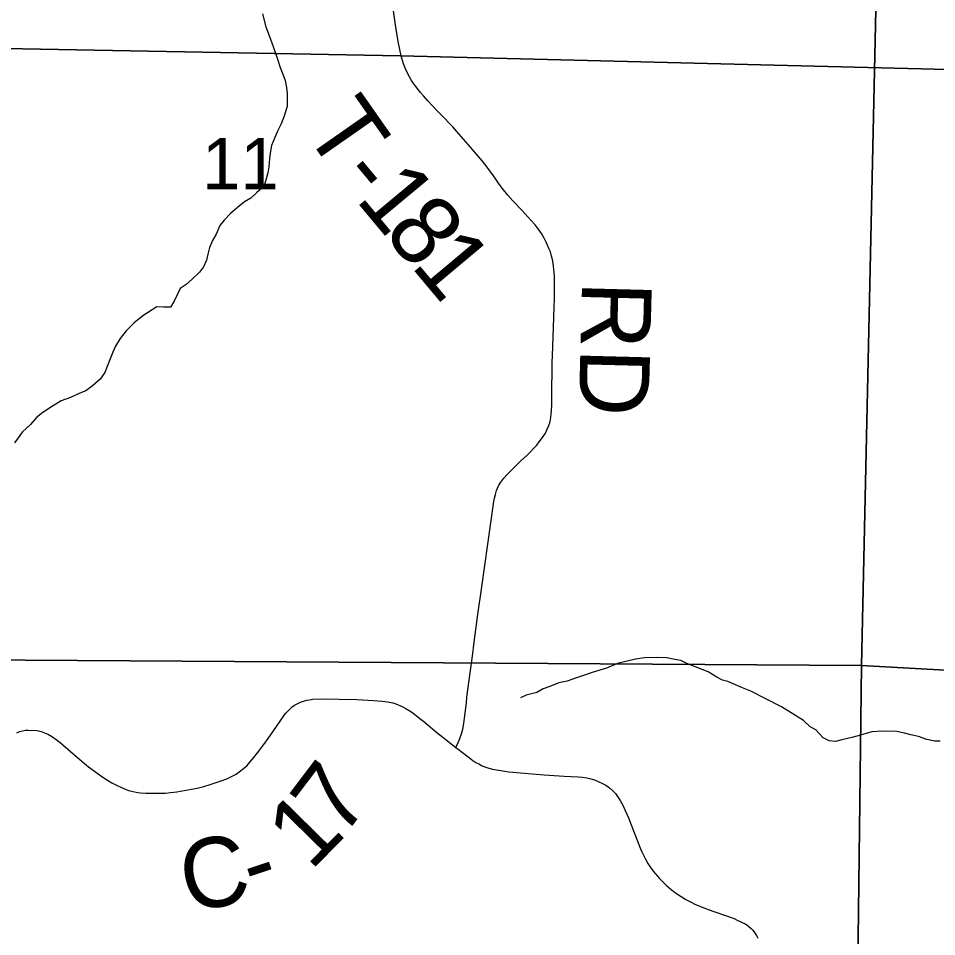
# Model space of a CAD drawing. Extents: x 0 to 34, y 0 to 22.
# Drawn here: x 13.784 to 14.532, y 16.764 to 17.512 of the extents above; entities that cross this region are included whole.
import ezdxf

# ---------------------------------------------------------------- set-up
doc = ezdxf.new("R2010")
doc.units = 0
for name, color, linetype in [('GM_X_Corporation', 7, 'Continuous'), ('GM_X_County_Road', 7, 'Continuous'), ('GM_X_County_Road_Text', 7, 'Continuous'), ('GM_X_Minor_River', 7, 'Continuous'), ('GM_X_Section_Text', 7, 'Continuous'), ('GM_X_Township_Road', 7, 'Continuous'), ('GM_X_Township_Road_Text', 7, 'Continuous')]:
    doc.layers.add(name, color=color, linetype=linetype)

msp = doc.modelspace()

# ---------------------------------------------------------------- linework, layer by layer
at = {"layer": 'GM_X_Corporation'}
for points in [[(13.27416, 17.49656), (14.09544, 17.48114), (14.72599, 17.4654), (14.75606, 17.4645), (15.84263, 17.42782), (15.88436, 17.42688), (16.48069, 17.41608), (16.48857, 17.73917), (16.51683, 18.87067), (16.5174, 18.89349), (16.54748, 18.89293), (16.75204, 18.88908), (16.75322, 19.06144), (16.75475, 19.28374), (16.76523, 20.32799), (16.7661, 20.4), (11.50006, 20.4)], [(16.44192, 14.8642), (16.44975, 15.46263), (16.45161, 15.59641), (16.46108, 16.1288), (16.46029, 16.26174), (16.46891, 16.92454), (16.47027, 17.00356), (16.4704, 17.01044), (16.48069, 17.41608), (15.88436, 17.42688), (15.84263, 17.42782), (14.75606, 17.4645), (14.72599, 17.4654), (14.09544, 17.48114), (13.27416, 17.49656)]]:
    msp.add_lwpolyline(points, dxfattribs=at)
for points in [[(13.4723, 18.00009), (14.4926, 17.9788), (14.47088, 16.98467), (13.4493, 16.99116)], [(14.4926, 17.9788), (15.50037, 17.94467), (15.48158, 16.92817), (14.47088, 16.98467)], [(13.4493, 16.99116), (14.47088, 16.98467), (14.45833, 15.96227), (13.43365, 15.97401)], [(14.47088, 16.98467), (15.48158, 16.92817), (15.46915, 15.91633), (14.45833, 15.96227)]]:
    msp.add_lwpolyline(points, close=True, dxfattribs=at)
at = {"layer": 'GM_X_County_Road'}
msp.add_lwpolyline([(13.78303, 16.92971), (13.78525, 16.93069), (13.78761, 16.93136), (13.7902, 16.93176), (13.7924, 16.9319), (13.79961, 16.93149), (13.80281, 16.93077), (13.80572, 16.92969), (13.80876, 16.92834), (13.81199, 16.92652), (13.81518, 16.92434), (13.81832, 16.92189), (13.82681, 16.91455), (13.83814, 16.90465), (13.84131, 16.90212), (13.84924, 16.89619), (13.85311, 16.89352), (13.85688, 16.89108), (13.8605, 16.88894), (13.86462, 16.88675), (13.8682, 16.88506), (13.87407, 16.8828), (13.87658, 16.88209), (13.8812, 16.88119), (13.88388, 16.88087), (13.88821, 16.88057), (13.892, 16.88046), (13.90407, 16.88065), (13.90815, 16.88096), (13.91335, 16.8816), (13.92521, 16.88367), (13.92986, 16.88466), (13.93533, 16.886), (13.9405, 16.88751), (13.94957, 16.8906), (13.95406, 16.89232), (13.95797, 16.89406), (13.96171, 16.89615), (13.96416, 16.89779), (13.96772, 16.90054), (13.97055, 16.90316), (13.97291, 16.90571), (13.97607, 16.90954), (13.981, 16.91589), (13.98645, 16.92328), (13.9915, 16.93063), (14.00099, 16.94436), (14.00208, 16.94572), (14.00576, 16.94961), (14.00721, 16.95083), (14.00919, 16.95221), (14.01174, 16.95362), (14.01408, 16.95467), (14.01646, 16.95552), (14.01919, 16.95627), (14.02139, 16.9567), (14.02396, 16.95703), (14.03145, 16.95741), (14.0598, 16.95677), (14.07342, 16.95608), (14.0804, 16.9555), (14.08491, 16.95492), (14.08921, 16.95404), (14.09157, 16.95326), (14.09676, 16.95104), (14.09973, 16.94949), (14.10257, 16.94782), (14.10537, 16.94596), (14.1113, 16.94141), (14.11439, 16.93883), (14.12496, 16.93002), (14.12982, 16.92618), (14.14054, 16.91787), (14.14348, 16.91557), (14.15301, 16.90837), (14.15446, 16.90705), (14.15692, 16.90558), (14.15916, 16.90438), (14.16196, 16.90288), (14.1642, 16.90197), (14.1673, 16.90096), (14.17044, 16.90017), (14.17875, 16.89866), (14.18362, 16.89805), (14.20271, 16.89628), (14.21244, 16.89548), (14.22885, 16.89447), (14.24001, 16.89384), (14.24364, 16.89352), (14.24721, 16.89299), (14.25052, 16.89226), (14.25355, 16.89128), (14.25653, 16.89003), (14.25994, 16.88843), (14.26256, 16.88697), (14.26576, 16.88479), (14.26834, 16.88243), (14.27047, 16.88024), (14.27226, 16.87793), (14.27432, 16.87468), (14.27641, 16.87075), (14.27848, 16.86641), (14.28104, 16.86055), (14.28341, 16.85464), (14.29086, 16.83531), (14.29195, 16.83279), (14.29491, 16.82664), (14.29675, 16.82337), (14.299, 16.81989), (14.30118, 16.81696), (14.30636, 16.81096), (14.30848, 16.80876), (14.31213, 16.80528), (14.31597, 16.80203), (14.3193, 16.79948), (14.32388, 16.79633), (14.32788, 16.79391), (14.33202, 16.79167), (14.33577, 16.78988), (14.33928, 16.78836), (14.34519, 16.78609), (14.36707, 16.77831), (14.36972, 16.7772), (14.37602, 16.77405), (14.37743, 16.77318), (14.38105, 16.77027), (14.38225, 16.76899), (14.38377, 16.76704), (14.38531, 16.76463), (14.38644, 16.76241)], dxfattribs=at)
at = {"layer": 'GM_X_Minor_River'}
for points in [[(13.98318, 17.51538), (13.98588, 17.50475), (13.99047, 17.49261), (13.99392, 17.48274), (13.99546, 17.47781), (13.99738, 17.47174), (13.99968, 17.46643), (14.00159, 17.46111), (14.00275, 17.45542), (14.00315, 17.45048), (14.00318, 17.44023), (14.00093, 17.43301), (13.9983, 17.42579), (13.99566, 17.42047), (13.99302, 17.41477), (13.99039, 17.40831), (13.98927, 17.40185), (13.98891, 17.3973), (13.98817, 17.39084), (13.98743, 17.3859), (13.98593, 17.37982), (13.98405, 17.37488), (13.97837, 17.36994), (13.97346, 17.36537), (13.96853, 17.36232), (13.96285, 17.35776), (13.95717, 17.35281), (13.95187, 17.34748), (13.94847, 17.34292), (13.94546, 17.33608), (13.94244, 17.33076), (13.93981, 17.32506), (13.93868, 17.31974), (13.93756, 17.3148), (13.93492, 17.30948), (13.9319, 17.30492), (13.92623, 17.29959), (13.92093, 17.29503), (13.916, 17.2916), (13.9111, 17.28134), (13.90808, 17.2764), (13.90239, 17.27639), (13.89707, 17.27675), (13.88571, 17.26952), (13.87851, 17.26381), (13.87208, 17.25734), (13.86717, 17.25088), (13.86339, 17.2448), (13.86113, 17.23985), (13.8585, 17.23302), (13.85474, 17.22314), (13.85096, 17.21781), (13.84453, 17.2121), (13.83922, 17.2083), (13.83429, 17.20639), (13.82671, 17.20296), (13.81913, 17.20028), (13.81117, 17.19534), (13.80435, 17.19077), (13.79905, 17.18658), (13.79414, 17.18087), (13.78771, 17.17479), (13.78128, 17.16604)], [(14.535, 16.9229), (14.53045, 16.92289), (14.52399, 16.9244), (14.51714, 16.92667), (14.51106, 16.92817), (14.50575, 16.92931), (14.49929, 16.93081), (14.48827, 16.93117), (14.47917, 16.93039), (14.46817, 16.92734), (14.46286, 16.92581), (14.45489, 16.92389), (14.44958, 16.92274), (14.44464, 16.92312), (14.4397, 16.92576), (14.4336, 16.93221), (14.42903, 16.93448), (14.4237, 16.93978), (14.41571, 16.94471), (14.40582, 16.95076), (14.38072, 16.96363), (14.37387, 16.96627), (14.36209, 16.97157), (14.35753, 16.9727), (14.35296, 16.97497), (14.34611, 16.97951), (14.33623, 16.98329), (14.32862, 16.98631), (14.32368, 16.98858), (14.31874, 16.98933), (14.31228, 16.99084), (14.30431, 16.9912), (14.29406, 16.9908), (14.28685, 16.98965), (14.27205, 16.98621), (14.26333, 16.98239), (14.25158, 16.97896), (14.24437, 16.97628), (14.23792, 16.97437), (14.2311, 16.9717), (14.22427, 16.97055), (14.21707, 16.9675), (14.21176, 16.96559), (14.20646, 16.96254), (14.19773, 16.96025), (14.19318, 16.95834)]]:
    msp.add_lwpolyline(points, dxfattribs=at)
at = {"layer": 'GM_X_Township_Road'}
for points in [[(14.09796, 17.47485), (14.09611, 17.48112), (14.09365, 17.49285), (14.09169, 17.50447), (14.08907, 17.52368), (14.08741, 17.53713), (14.08585, 17.55185), (14.08475, 17.56234)], [(14.15889, 17.39927), (14.15242, 17.4069), (14.14303, 17.4176), (14.13805, 17.42332), (14.13487, 17.42659), (14.1315, 17.43006), (14.12565, 17.43623), (14.12134, 17.44078), (14.11778, 17.44463), (14.11416, 17.44854), (14.1117, 17.45143), (14.10975, 17.45382), (14.10794, 17.45618), (14.10638, 17.45835), (14.10454, 17.46118), (14.10282, 17.46416), (14.10128, 17.46711), (14.09964, 17.47068), (14.09856, 17.47328), (14.09796, 17.47485)], [(14.14054, 16.91787), (14.14257, 16.92223), (14.14376, 16.92512), (14.14509, 16.92886), (14.14616, 16.93259), (14.14712, 16.93743), (14.14767, 16.94164), (14.14911, 16.95415), (14.1496, 16.95887), (14.15447, 16.99446), (14.15523, 17.00135), (14.15811, 17.02422), (14.16156, 17.04873), (14.17152, 17.11817), (14.17203, 17.12076), (14.1727, 17.12382), (14.1737, 17.12706), (14.17448, 17.12907), (14.17559, 17.13134), (14.17726, 17.13402), (14.17967, 17.13717), (14.18229, 17.14011), (14.18919, 17.14702), (14.19357, 17.15119), (14.19856, 17.15599), (14.20634, 17.16411), (14.20843, 17.16664), (14.21116, 17.17036), (14.21341, 17.17394), (14.21502, 17.177), (14.21638, 17.18021), (14.21703, 17.18227), (14.21755, 17.18457), (14.21811, 17.18904), (14.21856, 17.19631), (14.21873, 17.20335), (14.21902, 17.23098), (14.21937, 17.24416), (14.21967, 17.25264), (14.21994, 17.25938), (14.22034, 17.26877), (14.22065, 17.2768), (14.22085, 17.28263), (14.22099, 17.2927), (14.22078, 17.30171), (14.2206, 17.30471), (14.21973, 17.31227), (14.21914, 17.31536), (14.2185, 17.31803), (14.21747, 17.32147), (14.21662, 17.32381), (14.21524, 17.32689), (14.21405, 17.32957), (14.21235, 17.33277), (14.21021, 17.33638), (14.20757, 17.34029), (14.20499, 17.34365), (14.20172, 17.34749), (14.19426, 17.35551), (14.18704, 17.36317), (14.18296, 17.36771), (14.17925, 17.37221), (14.17585, 17.37677), (14.17299, 17.38085), (14.1711, 17.38355), (14.16811, 17.38767), (14.1661, 17.39044), (14.16213, 17.39545), (14.15889, 17.39927)]]:
    msp.add_lwpolyline(points, dxfattribs=at)

# ---------------------------------------------------------------- texts
at = {"layer": 'GM_X_County_Road_Text'}
for s, rotation, p in [('7', 52.90321, (14.04809, 16.84303)), ('1', 45.50527, (14.02229, 16.8166)), ('C', 11.09943, (13.92204, 16.78285)), ('-', 18.4115, (13.97549, 16.79385))]:
    msp.add_text(s, height=0.05682, rotation=rotation, dxfattribs=at).set_placement(p)
at = {"layer": 'GM_X_Section_Text'}
msp.add_text('11', height=0.041856, rotation=0.00001, dxfattribs=at).set_placement((13.93398, 17.37252))
at = {"layer": 'GM_X_Township_Road_Text'}
for s, height, rotation, p in [('T', 0.05682, 304.99764, (14.01565, 17.42106)), ('-', 0.05682, 309.83576, (14.0432, 17.38209)), ('1', 0.05682, 309.80824, (14.05814, 17.36418)), ('8', 0.05682, 309.83275, (14.08057, 17.33727)), ('1', 0.05682, 310.0116, (14.10311, 17.31024)), ('RD', 0.056818, 268.51936, (14.24339, 17.29813))]:
    msp.add_text(s, height=height, rotation=rotation, dxfattribs=at).set_placement(p)

doc.saveas('drawing.dxf')
